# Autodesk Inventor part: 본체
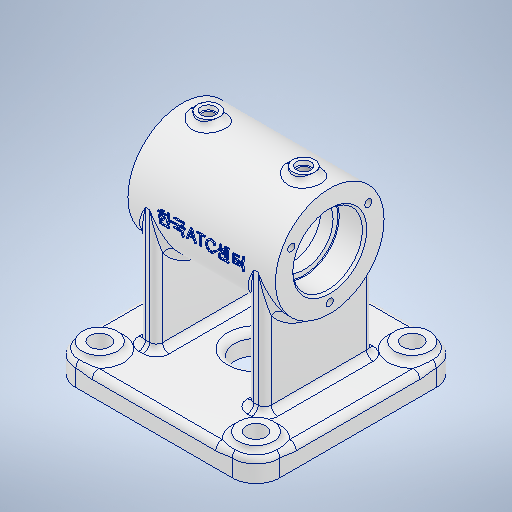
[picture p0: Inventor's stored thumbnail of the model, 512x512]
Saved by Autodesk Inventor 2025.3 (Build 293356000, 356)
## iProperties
Created: 2025-10
Part Number: 본체
Material: 알루미늄 6061
Document SubType Name: Modeling
Designer: USER
Density: 2.7 g/cm^3
Appearance: 알루미늄 - 평지
Mass: 504.67 g
Surface Area: 500.812 cm^2
Volume: 186.915 cm^3
Author: USER
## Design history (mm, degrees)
sketch "스케치1"
  geometry: L1 (-34, 0)-(34, 0); L2 (-34, 0)-(-34, 16); L3 (-34, 16)-(-22.3, 16); L4 (-22, 15.7)-(-22, 13.5); L5 (-22, 13.5)-(-16.258, 13.5); L6 (-16.258, 13.5)-(-5, 20); L7 (-5, 20)-(5, 20); L8 (5, 20)-(16.258, 13.5); L9 (16.258, 13.5)-(22, 13.5); L10 (22, 13.5)-(22, 15.7); L11 (22.3, 16)-(34, 16); L12 (34, 16)-(34, 0); L13 (-34, 25)-(34, 25); L14 (-34, 25)-(-34, 16); L15 (34, 25)-(34, 16); A1 r 0.3 centre (-22.3, 15.7) between (-22, 15.7) and (-22.3, 16); A2 r 0.3 centre (22.3, 15.7) between (22.3, 16) and (22, 15.7); 3 further points
  constraints: 30 end point, 6 perpendicular, 4 point on circle, 4 tangent, 3 vertical, 3 vertical alignment, 2 centre point, 2 coincident, 2 midpoint, 2 point on line, 1 equal radius, 1 horizontal, 1 parallel
  dimensions: "d0" = 12 distance between parallel lines of L4 L2; "d1" = 32 diameter of L3 L1; "d2" = 27 diameter of L5 L1; "d3" = 40 diameter of L7 L1; "d4" = 30 deg angle of L1 L6; "d5" = 30 deg angle of L1 L8; "d6" = 10 distance of L7.end L6.end; "d8" = 32 diameter of L11 L1; "d9" = 12 distance between parallel lines of L10 L12; "d10" = 68 distance between parallel lines of L12 L2; "d11" = 50 diameter of L13 L1; "d12" = 0.3 radius of A1 (derived)
revolve "회전1" sketch "스케치1" stored, may be unused: angle "d13" = 90 deg
node "작업 평면1"
sketch "스케치2"
  geometry: L1 (36, -47)-(-36, -47); L2 (-47, -36)-(-47, 36); L3 (-36, 47)-(36, 47); L4 (47, 36)-(47, -36); L5 (47, -47)-(-47, 47); L6 (-47, -47)-(47, 47); A1 r 11 centre (-36, 36) between (-36, 47) and (-47, 36); A2 r 11 centre (36, 36) between (47, 36) and (36, 47); A3 r 11 centre (36, -36) between (36, -47) and (47, -36); A4 r 11 centre (-36, -36) between (-47, -36) and (-36, -47); 1 further point
  constraints: 12 end point, 8 point on circle, 8 point on line, 8 tangent, 4 centre point, 2 equal radius, 2 midpoint, 2 parallel, 1 horizontal, 1 perpendicular
  dimensions: "d15" = 94 distance between parallel lines of L1 L3; "d16" = 94 distance between parallel lines of L2 L4; "d17" = 11 radius of A1; "d18" = 11 radius of A2
extrude "돌출1" join sketch "스케치2" distance "d19" = 10; taper "d20" = 0 deg
sketch "스케치4"
  geometry: L1 (-36, -47)-(36, -47) reference; L2 (47, -36)-(47, 36) reference; L3 (-36, -47)-(36, -47) reference; L4 (-47, 36)-(-47, -36) reference; L5 (36, 47)-(-36, 47) reference; L6 (47, -36)-(47, 36) reference; C1 r 8 at (36, -36); C2 r 8 at (-36, -36); C3 r 8 at (-36, 36); C4 r 8 at (36, 36); A1 r 11 centre (36, -36) between (36, -47) and (47, -36) reference; A2 r 11 centre (-36, -36) between (-47, -36) and (-36, -47) reference; A3 r 11 centre (-36, 36) between (-36, 47) and (-47, 36) reference; A4 r 11 centre (36, 36) between (47, 36) and (36, 47) reference; A5 r 11 centre (36, -36) between (36, -47) and (47, -36) reference; 1 further point
  constraints: 4 centre point, 4 coincident
  dimensions: "d29" = 16 diameter of C1; "d30" = 16 diameter of C2; "d31" = 16 diameter of C3; "d32" = 16 diameter of C4
extrude "돌출3" join sketch "스케치4" distance "d33" = 3; taper "d34" = 0 deg
sketch "스케치5"
  geometry: C1 r 8 at (-72, 0) reference; C2 r 8 at (0, 0) reference; C3 r 8 at (0, 72) reference; C4 r 8 at (-72, 72) reference; C5 r 4.5 at (-72, 0); C6 r 4.5 at (0, 0); C7 r 4.5 at (0, 72); C8 r 4.5 at (-72, 72); 1 further point
  constraints: 4 centre point, 4 coincident
  dimensions: "d35" = 9 diameter of C5; "d36" = 9 diameter of C6; "d37" = 9 diameter of C7; "d38" = 9 diameter of C8
extrude "돌출4" cut sketch "스케치5" extent not by distance; stored distance "d39" = 0; taper "d40" = 0 deg
node "작업 평면2"
sketch "스케치6"
  geometry: L1 (34, 25)-(34, -25) reference; L2 (-34, 25)-(-34, -25) reference; C1 r 5 at (22, 0); C2 r 5 at (-22, 0); 1 further point
  constraints: 2 centre point, 2 horizontal alignment
  dimensions: "d41" = 12 distance from line of C1.centre L1; "d42" = 12 distance from line of C2.centre L2; "d43" = 10 diameter of C1; "d44" = 10 diameter of C2
extrude "돌출5" join sketch "스케치6" stored distance "d45" = 10; taper "d46" = 0 deg
extrude "돌출6" join sketch "스케치6" distance "d47" = 3; taper "d48" = 0 deg
sketch "스케치7"
  geometry: C1 r 5 at (0, 0) reference; C2 r 5 at (44, 0) reference; C3 r 3.3 at (0, 0); C4 r 3.3 at (44, 0); 1 further point
  constraints: 2 centre point, 2 coincident
  dimensions: "d49" = 6.6 diameter of C3; "d50" = 6.6 diameter of C4
extrude "돌출7" cut sketch "스케치7" distance "d51" = 2; taper "d52" = 0 deg
sketch "스케치8"
  geometry: C1 r 3.3 at (0, 0) reference; C2 r 3.3 at (44, 0) reference; 3 further points
  constraints: 2 coincident
hole "구멍1" sketch "스케치8" at (0, 0), (44, 0) diameter "d53" = 5.1881; stored, may be unused: countersink angle "d57" = 90 deg, drill point angle "d59" = 0 deg; dims "d54" = 12, "d55" = 4, "d56" = 2, "d58" = 16
node "작업 평면3"
sketch "스케치9"
  geometry: C1 r 6 at (0, 0); 1 further point
  constraints: 1 centre point, 1 coincident
  dimensions: "d60" = 12 diameter of C1
extrude "돌출8" join sketch "스케치9" stored distance "d61" = 10; taper "d62" = 0 deg
extrude "돌출9" join sketch "스케치9" distance "d63" = 3; taper "d64" = 0 deg
sketch "스케치10"
  geometry: 1 further point
hole "구멍2" sketch "스케치10" at (0, 0) diameter "d65" = 5.1881; stored, may be unused: countersink angle "d69" = 90 deg, drill point angle "d71" = 0 deg; dims "d66" = 12, "d67" = 4, "d68" = 2, "d70" = 16
sketch "스케치11"
  geometry: C1 r 25 at (0, 0) reference; C2 r 0.5 at (0, -20.5); C3 r 0.5 at (17.754, 10.25); C4 r 0.5 at (-17.754, 10.25); 2 further points
  constraints: 3 centre point, 2 vertical alignment, 1 coincident, 9 other
  dimensions: "d72" = 4.5 dimension on C1; "d73" = 1 diameter of C2; "d76" = 360 deg dimension on point (0, 0) C2.centre (derived)
hole "구멍3" sketch "스케치11" at (-17.754, 10.25), (0, -20.5), (17.754, 10.25) diameter "d78" = 3.242; stored, may be unused: countersink angle "d82" = 90 deg, drill point angle "d84" = 118 deg; dims "d79" = 8, "d80" = 4, "d81" = 2, "d83" = 10
sketch "스케치12"
  geometry: C1 r 10 at (0, 0); 1 further point
  constraints: 1 centre point, 1 coincident
  dimensions: "d85" = 20 diameter of C1
extrude "돌출10" cut sketch "스케치12" extent not by distance; stored distance "d86" = 0; taper "d87" = 0 deg
sketch "스케치13"
  geometry: L1 (26, -25)-(24, -25); L2 (21, -22)-(21, 22); L3 (24, 25)-(26, 25); L4 (29, 22)-(29, -22); L5 (-24, -25)-(-26, -25); L6 (-29, -22)-(-29, 22); L7 (-26, 25)-(-24, 25); L8 (-21, 22)-(-21, -22); A1 r 3 centre (26, -22) between (26, -25) and (29, -22); A2 r 3 centre (24, -22) between (21, -22) and (24, -25); A3 r 3 centre (24, 22) between (24, 25) and (21, 22); A4 r 3 centre (26, 22) between (29, 22) and (26, 25); A5 r 3 centre (-24, -22) between (-24, -25) and (-21, -22); A6 r 3 centre (-26, -22) between (-29, -22) and (-26, -25); A7 r 3 centre (-26, 22) between (-26, 25) and (-29, 22); A8 r 3 centre (-24, 22) between (-21, 22) and (-24, 25); 4 further points
  constraints: 16 end point, 16 point on circle, 16 tangent, 8 centre point, 6 equal radius, 4 parallel, 2 horizontal, 2 horizontal alignment, 2 midpoint, 2 perpendicular
  dimensions: "d96" = 8 distance between parallel lines of L2 L4; "d97" = 50 distance between parallel lines of L3 L1; "d98" = 3 radius of A1 (derived); "d99" = 8 distance between parallel lines of L6 L8; "d100" = 50 distance between parallel lines of L7 L5; "d101" = 3 radius of A5 (derived); "d102" = 21 distance from line of L2 point (0, 0); "d103" = 42 distance between parallel lines of L8 L2
extrude "돌출11" join sketch "스케치13" stored distance "d104" = 10; taper "d105" = 0 deg
fillet "모깎기1" dims "d106" = 3
sketch "스케치14"
  geometry: L1 (-43.455, 8.276)-(43.455, 8.276); L2 (43.455, 8.276)-(43.455, -8.276); L3 (43.455, -8.276)-(-43.455, -8.276); L4 (-43.455, -8.276)-(-43.455, 8.276); 3 further points
  constraints: 2 midpoint, 1 horizontal alignment, 1 vertical alignment, 2 other
feature "엠보싱1" sketch "스케치14" dims "d107" = 0.5, "d108" = 0
chamfer "모따기1" distance "d109" = 1; stored, may be unused: second distance "d110" = 2, angle "d111" = 45 deg
node "솔리드1"
mirror "미러1"
node "투영된 루프1"
node "투영된 루프2"
node "투영된 루프3"
node "스케치 - 원형 패턴1" dims "d76" = 360 deg (derived)
feature "A9D066F2-1C7D-4E18-AEED-F7BC21143FA4" dims "d65" = 5.1881, "d66" = 12, "d67" = 4, "d68" = 2, "d69" = 90 deg, "d70" = 16, "d71" = 0
other parameters: "d14" = -66
